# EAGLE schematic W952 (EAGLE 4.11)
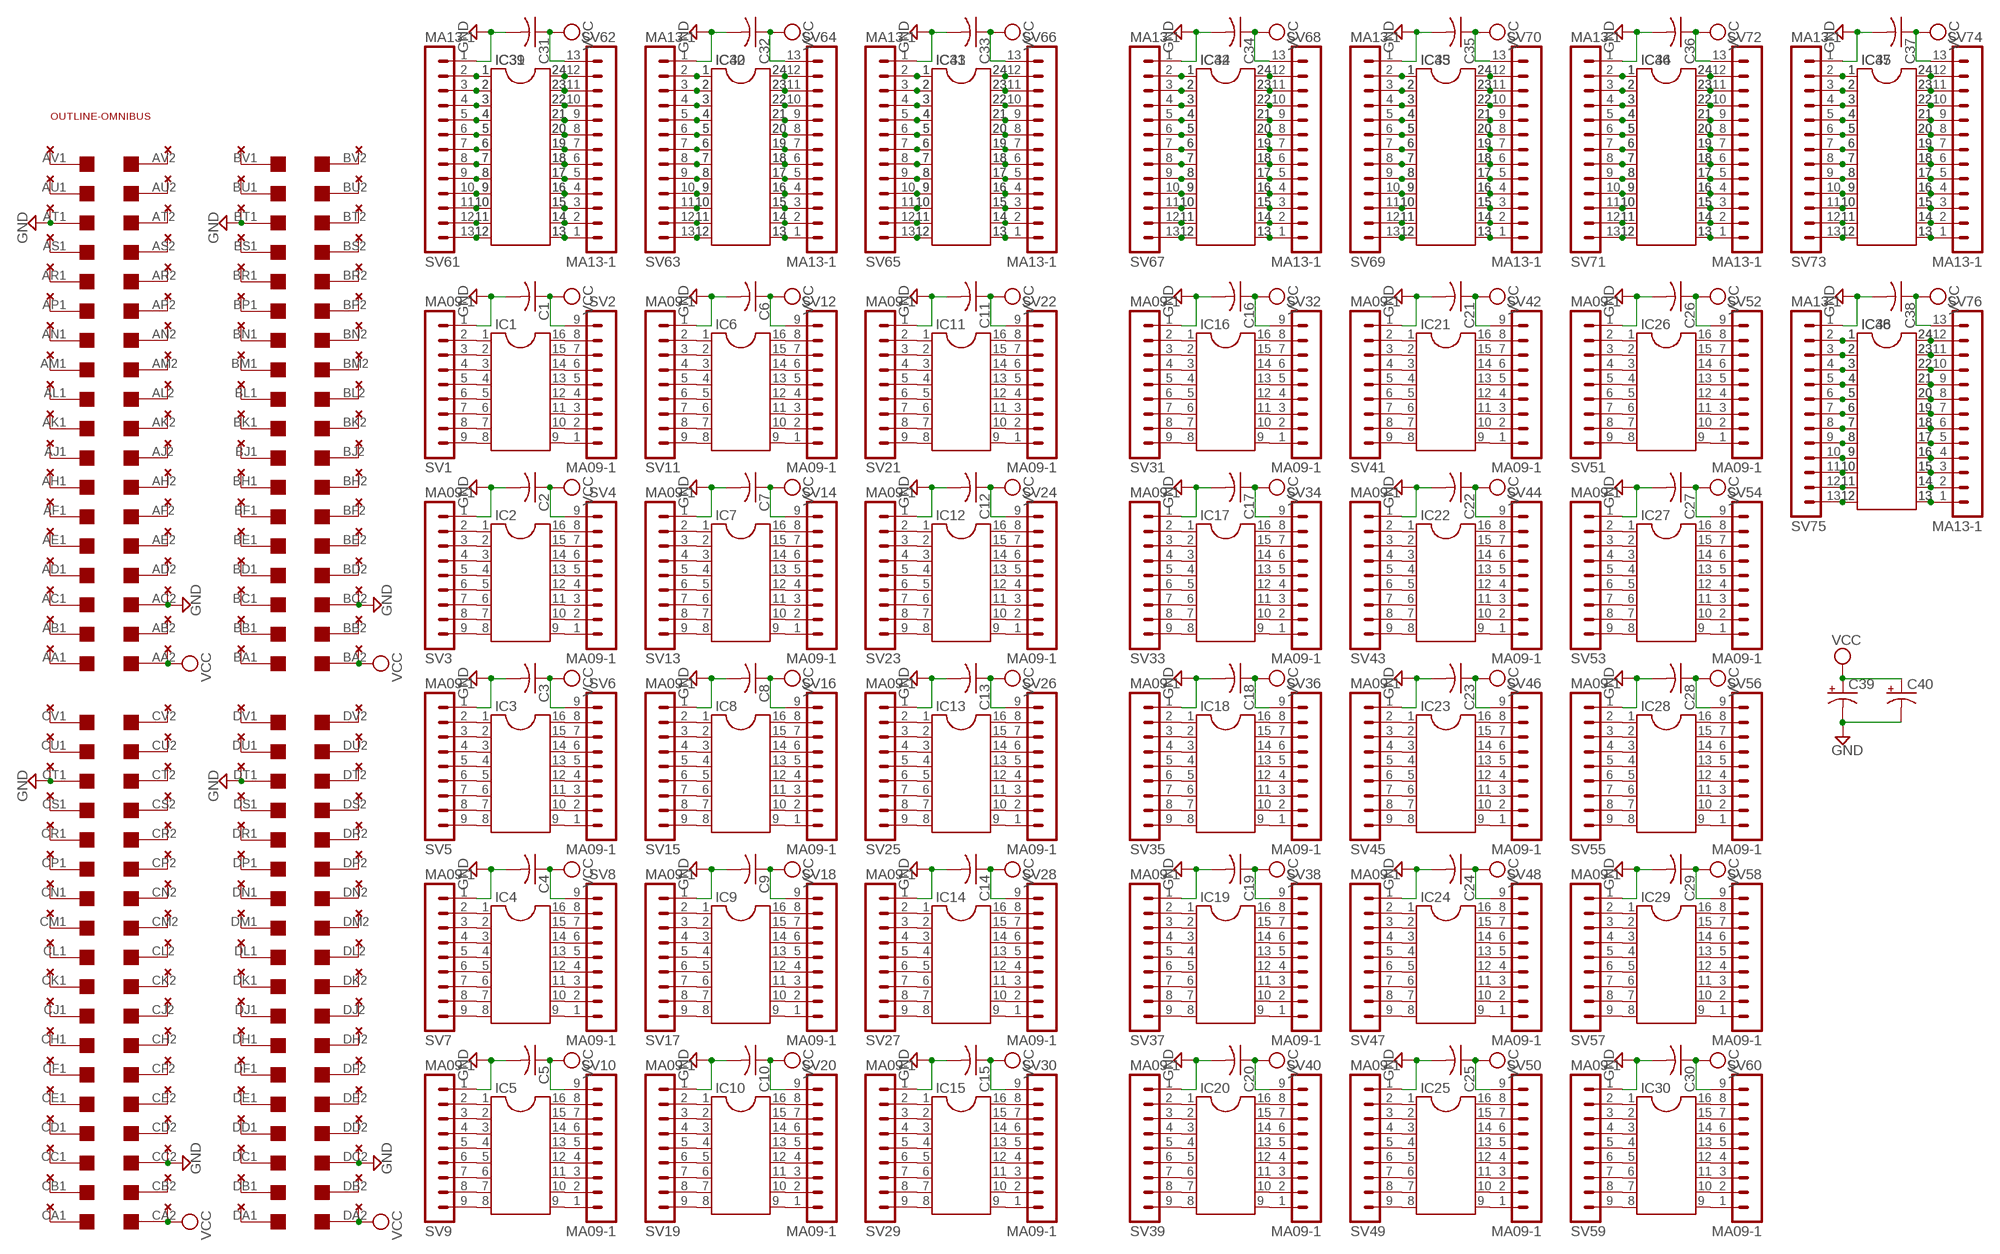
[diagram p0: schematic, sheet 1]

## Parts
C1  C-US075-032X103  [C075-032X103]
C2  C-US075-032X103  [C075-032X103]
C3  C-US075-032X103  [C075-032X103]
C4  C-US075-032X103  [C075-032X103]
C5  C-US075-032X103  [C075-032X103]
C6  C-US075-032X103  [C075-032X103]
C7  C-US075-032X103  [C075-032X103]
C8  C-US075-032X103  [C075-032X103]
C9  C-US075-032X103  [C075-032X103]
C10  C-US075-032X103  [C075-032X103]
C11  C-US075-032X103  [C075-032X103]
C12  C-US075-032X103  [C075-032X103]
C13  C-US075-032X103  [C075-032X103]
C14  C-US075-032X103  [C075-032X103]
C15  C-US075-032X103  [C075-032X103]
C16  C-US075-032X103  [C075-032X103]
C17  C-US075-032X103  [C075-032X103]
C18  C-US075-032X103  [C075-032X103]
C19  C-US075-032X103  [C075-032X103]
C20  C-US075-032X103  [C075-032X103]
C21  C-US075-032X103  [C075-032X103]
C22  C-US075-032X103  [C075-032X103]
C23  C-US075-032X103  [C075-032X103]
C24  C-US075-032X103  [C075-032X103]
C25  C-US075-032X103  [C075-032X103]
C26  C-US075-032X103  [C075-032X103]
C27  C-US075-032X103  [C075-032X103]
C28  C-US075-032X103  [C075-032X103]
C29  C-US075-032X103  [C075-032X103]
C30  C-US075-032X103  [C075-032X103]
C31  C-US075-032X103  [C075-032X103]
C32  C-US075-032X103  [C075-032X103]
C33  C-US075-032X103  [C075-032X103]
C34  C-US075-032X103  [C075-032X103]
C35  C-US075-032X103  [C075-032X103]
C36  C-US075-032X103  [C075-032X103]
C37  C-US075-032X103  [C075-032X103]
C38  C-US075-032X103  [C075-032X103]
C39  CPOL-USE15-5AXIAL  [E15-5]
C40  CPOL-USE15-5AXIAL  [E15-5]
IC1  DIL16S  [SOCKED-16]
IC2  DIL16S  [SOCKED-16]
IC3  DIL16S  [SOCKED-16]
IC4  DIL16S  [SOCKED-16]
IC5  DIL16S  [SOCKED-16]
IC6  DIL16S  [SOCKED-16]
IC7  DIL16S  [SOCKED-16]
IC8  DIL16S  [SOCKED-16]
IC9  DIL16S  [SOCKED-16]
IC10  DIL16S  [SOCKED-16]
IC11  DIL16S  [SOCKED-16]
IC12  DIL16S  [SOCKED-16]
IC13  DIL16S  [SOCKED-16]
IC14  DIL16S  [SOCKED-16]
IC15  DIL16S  [SOCKED-16]
IC16  DIL16S  [SOCKED-16]
IC17  DIL16S  [SOCKED-16]
IC18  DIL16S  [SOCKED-16]
IC19  DIL16S  [SOCKED-16]
IC20  DIL16S  [SOCKED-16]
IC21  DIL16S  [SOCKED-16]
IC22  DIL16S  [SOCKED-16]
IC23  DIL16S  [SOCKED-16]
IC24  DIL16S  [SOCKED-16]
IC25  DIL16S  [SOCKED-16]
IC26  DIL16S  [SOCKED-16]
IC27  DIL16S  [SOCKED-16]
IC28  DIL16S  [SOCKED-16]
IC29  DIL16S  [SOCKED-16]
IC30  DIL16S  [SOCKED-16]
IC31  DIL24-6  [DIL24-6]
IC32  DIL24-6  [DIL24-6]
IC33  DIL24-6  [DIL24-6]
IC34  DIL24-6  [DIL24-6]
IC35  DIL24-6  [DIL24-6]
IC36  DIL24-6  [DIL24-6]
IC37  DIL24-6  [DIL24-6]
IC38  DIL24-6  [DIL24-6]
IC39  DIL24-3  [DIL24-3]
IC40  DIL24-3  [DIL24-3]
IC41  DIL24-3  [DIL24-3]
IC42  DIL24-3  [DIL24-3]
IC43  DIL24-3  [DIL24-3]
IC44  DIL24-3  [DIL24-3]
IC45  DIL24-3  [DIL24-3]
IC46  DIL24-3  [DIL24-3]
SV1  MA09-1  [MA09-1]
SV2  MA09-1  [MA09-1]
SV3  MA09-1  [MA09-1]
SV4  MA09-1  [MA09-1]
SV5  MA09-1  [MA09-1]
SV6  MA09-1  [MA09-1]
SV7  MA09-1  [MA09-1]
SV8  MA09-1  [MA09-1]
SV9  MA09-1  [MA09-1]
SV10  MA09-1  [MA09-1]
SV11  MA09-1  [MA09-1]
SV12  MA09-1  [MA09-1]
SV13  MA09-1  [MA09-1]
SV14  MA09-1  [MA09-1]
SV15  MA09-1  [MA09-1]
SV16  MA09-1  [MA09-1]
SV17  MA09-1  [MA09-1]
SV18  MA09-1  [MA09-1]
SV19  MA09-1  [MA09-1]
SV20  MA09-1  [MA09-1]
SV21  MA09-1  [MA09-1]
SV22  MA09-1  [MA09-1]
SV23  MA09-1  [MA09-1]
SV24  MA09-1  [MA09-1]
SV25  MA09-1  [MA09-1]
SV26  MA09-1  [MA09-1]
SV27  MA09-1  [MA09-1]
SV28  MA09-1  [MA09-1]
SV29  MA09-1  [MA09-1]
SV30  MA09-1  [MA09-1]
SV31  MA09-1  [MA09-1]
SV32  MA09-1  [MA09-1]
SV33  MA09-1  [MA09-1]
SV34  MA09-1  [MA09-1]
SV35  MA09-1  [MA09-1]
SV36  MA09-1  [MA09-1]
SV37  MA09-1  [MA09-1]
SV38  MA09-1  [MA09-1]
SV39  MA09-1  [MA09-1]
SV40  MA09-1  [MA09-1]
SV41  MA09-1  [MA09-1]
SV42  MA09-1  [MA09-1]
SV43  MA09-1  [MA09-1]
SV44  MA09-1  [MA09-1]
SV45  MA09-1  [MA09-1]
SV46  MA09-1  [MA09-1]
SV47  MA09-1  [MA09-1]
SV48  MA09-1  [MA09-1]
SV49  MA09-1  [MA09-1]
SV50  MA09-1  [MA09-1]
SV51  MA09-1  [MA09-1]
SV52  MA09-1  [MA09-1]
SV53  MA09-1  [MA09-1]
SV54  MA09-1  [MA09-1]
SV55  MA09-1  [MA09-1]
SV56  MA09-1  [MA09-1]
SV57  MA09-1  [MA09-1]
SV58  MA09-1  [MA09-1]
SV59  MA09-1  [MA09-1]
SV60  MA09-1  [MA09-1]
SV61  MA13-1  [MA13-1]
SV62  MA13-1  [MA13-1]
SV63  MA13-1  [MA13-1]
SV64  MA13-1  [MA13-1]
SV65  MA13-1  [MA13-1]
SV66  MA13-1  [MA13-1]
SV67  MA13-1  [MA13-1]
SV68  MA13-1  [MA13-1]
SV69  MA13-1  [MA13-1]
SV70  MA13-1  [MA13-1]
SV71  MA13-1  [MA13-1]
SV72  MA13-1  [MA13-1]
SV73  MA13-1  [MA13-1]
SV74  MA13-1  [MA13-1]
SV75  MA13-1  [MA13-1]
SV76  MA13-1  [MA13-1]
U$1  QUAD  [EDGE-CON8]
U$2  THRU-HOLE2  [THRU-HOLE2]
U$3  THRU-HOLE2  [THRU-HOLE2]
U$4  THRU-HOLE2  [THRU-HOLE2]
U$5  THRU-HOLE2  [THRU-HOLE2]
U$8  OUTLINE-OMNIBUS  [OMNIBUS]

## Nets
GND [supply]: C1.2 C2.2 C3.2 C4.2 C5.2 C6.2 C7.2 C8.2 C9.2 C10.2 C11.2 C12.2 C13.2 C14.2 C15.2 C16.2 C17.2 C18.2 C19.2 C20.2 C21.2 C22.2 C23.2 C24.2 C25.2 C26.2 C27.2 C28.2 C29.2 C30.2 C31.2 C32.2 C33.2 C34.2 C35.2 C36.2 C37.2 C38.2 C39.- C40.- SV1.1 SV3.1 SV5.1 SV7.1 SV9.1 SV11.1 SV13.1 SV15.1 SV17.1 SV19.1 SV21.1 SV23.1 SV25.1 SV27.1 SV29.1 SV31.1 SV33.1 SV35.1 SV37.1 SV39.1 SV41.1 SV43.1 SV45.1 SV47.1 SV49.1 SV51.1 SV53.1 SV55.1 SV57.1 SV59.1 SV61.1 SV63.1 SV65.1 SV67.1 SV69.1 SV71.1 SV73.1 SV75.1 U$1.AC2 U$1.AT1 U$1.BC2 U$1.BT1 U$1.CC2 U$1.CT1 U$1.DC2 U$1.DT1 U$2.C1 U$2.T2 U$3.C1 U$3.T2 U$4.C1 U$4.T2 U$5.C1 U$5.T2
N$1: U$1.AK1 U$2.K2
N$2: U$1.AJ1 U$2.J2
N$3: U$1.AH1 U$2.H2
N$4: U$1.AL1 U$2.L2
N$5: U$1.AM1 U$2.M2
N$6: U$1.AN1 U$2.N2
N$7: U$1.AP1 U$2.P2
N$8: U$1.AF1 U$2.F2
N$9: U$1.AE1 U$2.E2
N$10: U$1.AD1 U$2.D2
N$11: U$1.AC1 U$2.C2
N$12: U$1.AR1 U$2.R2
N$13: U$1.AS1 U$2.S2
N$14: U$1.AB1 U$2.B2
N$15: U$1.AA1 U$2.A2
N$16: U$1.AU1 U$2.U2
N$17: U$1.AV1 U$2.V2
N$18: U$1.AV2 U$2.V1
N$19: U$1.AU2 U$2.U1
N$20: U$1.AT2 U$2.T1
N$21: U$1.AS2 U$2.S1
N$22: U$1.AR2 U$2.R1
N$23: U$1.AP2 U$2.P1
N$24: U$1.AN2 U$2.N1
N$25: U$1.AM2 U$2.M1
N$26: U$1.AL2 U$2.L1
N$27: U$1.AK2 U$2.K1
N$28: U$1.AJ2 U$2.J1
N$29: U$1.AH2 U$2.H1
N$30: U$1.AF2 U$2.F1
N$31: U$1.AE2 U$2.E1
N$32: U$1.AD2 U$2.D1
N$33: U$1.AB2 U$2.B1
N$34: U$1.BV1 U$3.V2
N$35: U$1.BU1 U$3.U2
N$36: U$1.BS1 U$3.S2
N$37: U$1.BR1 U$3.R2
N$38: U$1.BP1 U$3.P2
N$39: U$1.BN1 U$3.N2
N$40: U$1.BM1 U$3.M2
N$41: U$1.BL1 U$3.L2
N$42: U$1.BK1 U$3.K2
N$43: U$1.BJ1 U$3.J2
N$44: U$1.BH1 U$3.H2
N$45: U$1.BF1 U$3.F2
N$46: U$1.BE1 U$3.E2
N$47: U$1.BD1 U$3.D2
N$48: U$1.BC1 U$3.C2
N$49: U$1.BB1 U$3.B2
N$50: U$1.BA1 U$3.A2
N$51: U$1.BV2 U$3.V1
N$52: U$1.BU2 U$3.U1
N$53: U$1.BT2 U$3.T1
N$54: U$1.BS2 U$3.S1
N$55: U$1.BR2 U$3.R1
N$56: U$1.BP2 U$3.P1
N$57: U$1.BN2 U$3.N1
N$58: U$1.BM2 U$3.M1
N$59: U$1.BL2 U$3.L1
N$60: U$1.BK2 U$3.K1
N$61: U$1.BJ2 U$3.J1
N$62: U$1.BH2 U$3.H1
N$63: U$1.BF2 U$3.F1
N$64: U$1.BE2 U$3.E1
N$65: U$1.BD2 U$3.D1
N$66: U$1.BB2 U$3.B1
N$67: U$1.CV1 U$4.V2
N$68: U$1.CU1 U$4.U2
N$69: U$1.CS1 U$4.S2
N$70: U$1.CR1 U$4.R2
N$71: U$1.CP1 U$4.P2
N$72: U$1.CN1 U$4.N2
N$73: U$1.CM1 U$4.M2
N$74: U$1.CL1 U$4.L2
N$75: U$1.CK1 U$4.K2
N$76: U$1.CJ1 U$4.J2
N$77: U$1.CH1 U$4.H2
N$78: U$1.CF1 U$4.F2
N$79: U$1.CE1 U$4.E2
N$80: U$1.CD1 U$4.D2
N$81: U$1.CC1 U$4.C2
N$82: U$1.CB1 U$4.B2
N$83: U$1.CA1 U$4.A2
N$84: U$1.CV2 U$4.V1
N$85: U$1.CU2 U$4.U1
N$86: U$1.CT2 U$4.T1
N$87: U$1.CS2 U$4.S1
N$88: U$1.CR2 U$4.R1
N$89: U$1.CP2 U$4.P1
N$90: U$1.CN2 U$4.N1
N$91: U$1.CM2 U$4.M1
N$92: U$1.CL2 U$4.L1
N$93: U$1.CK2 U$4.K1
N$94: U$1.CJ2 U$4.J1
N$95: U$1.CH2 U$4.H1
N$96: U$1.CF2 U$4.F1
N$97: U$1.CE2 U$4.E1
N$98: U$1.CD2 U$4.D1
N$99: U$1.CB2 U$4.B1
N$100: U$1.DV1 U$5.V2
N$101: U$1.DU1 U$5.U2
N$102: U$1.DS1 U$5.S2
N$103: U$1.DR1 U$5.R2
N$104: U$1.DP1 U$5.P2
N$105: U$1.DN1 U$5.N2
N$106: U$1.DM1 U$5.M2
N$107: U$1.DL1 U$5.L2
N$108: U$1.DK1 U$5.K2
N$109: U$1.DJ1 U$5.J2
N$110: U$1.DH1 U$5.H2
N$111: U$1.DF1 U$5.F2
N$112: U$1.DE1 U$5.E2
N$113: U$1.DD1 U$5.D2
N$114: U$1.DC1 U$5.C2
N$115: U$1.DB1 U$5.B2
N$116: U$1.DA1 U$5.A2
N$117: U$1.DV2 U$5.V1
N$118: U$1.DU2 U$5.U1
N$119: U$1.DT2 U$5.T1
N$120: U$1.DS2 U$5.S1
N$121: U$1.DR2 U$5.R1
N$122: U$1.DP2 U$5.P1
N$123: U$1.DN2 U$5.N1
N$124: U$1.DM2 U$5.M1
N$125: U$1.DL2 U$5.L1
N$126: U$1.DK2 U$5.K1
N$127: U$1.DJ2 U$5.J1
N$128: U$1.DH2 U$5.H1
N$129: U$1.DF2 U$5.F1
N$130: U$1.DE2 U$5.E1
N$131: U$1.DD2 U$5.D1
N$132: U$1.DB2 U$5.B1
N$133: IC1.1 SV1.2
N$134: IC1.2 SV1.3
N$135: IC1.3 SV1.4
N$136: IC1.4 SV1.5
N$137: IC1.5 SV1.6
N$138: IC1.6 SV1.7
N$139: IC1.7 SV1.8
N$140: IC1.8 SV1.9
N$141: IC1.9 SV2.1
N$142: IC1.10 SV2.2
N$143: IC1.11 SV2.3
N$144: IC1.12 SV2.4
N$145: IC1.13 SV2.5
N$146: IC1.14 SV2.6
N$147: IC1.15 SV2.7
N$148: IC1.16 SV2.8
N$151: IC2.1 SV3.2
N$152: IC2.2 SV3.3
N$153: IC2.3 SV3.4
N$154: IC2.4 SV3.5
N$155: IC2.5 SV3.6
N$156: IC2.6 SV3.7
N$157: IC2.7 SV3.8
N$158: IC2.8 SV3.9
N$159: IC2.9 SV4.1
N$160: IC2.10 SV4.2
N$161: IC2.11 SV4.3
N$162: IC2.12 SV4.4
N$163: IC2.13 SV4.5
N$164: IC2.14 SV4.6
N$165: IC2.15 SV4.7
N$166: IC2.16 SV4.8
N$169: IC3.1 SV5.2
N$170: IC3.2 SV5.3
N$171: IC3.3 SV5.4
N$172: IC3.4 SV5.5
N$173: IC3.5 SV5.6
N$174: IC3.6 SV5.7
N$175: IC3.7 SV5.8
N$176: IC3.8 SV5.9
N$177: IC3.9 SV6.1
N$178: IC3.10 SV6.2
N$179: IC3.11 SV6.3
N$180: IC3.12 SV6.4
N$181: IC3.13 SV6.5
N$182: IC3.14 SV6.6
N$183: IC3.15 SV6.7
N$184: IC3.16 SV6.8
N$187: IC4.1 SV7.2
N$188: IC4.2 SV7.3
N$189: IC4.3 SV7.4
N$190: IC4.4 SV7.5
N$191: IC4.5 SV7.6
N$192: IC4.6 SV7.7
N$193: IC4.7 SV7.8
N$194: IC4.8 SV7.9
N$195: IC4.9 SV8.1
N$196: IC4.10 SV8.2
N$197: IC4.11 SV8.3
N$198: IC4.12 SV8.4
N$199: IC4.13 SV8.5
N$200: IC4.14 SV8.6
N$201: IC4.15 SV8.7
N$202: IC4.16 SV8.8
N$205: IC5.1 SV9.2
N$206: IC5.2 SV9.3
N$207: IC5.3 SV9.4
N$208: IC5.4 SV9.5
N$209: IC5.5 SV9.6
N$210: IC5.6 SV9.7
N$211: IC5.7 SV9.8
N$212: IC5.8 SV9.9
N$213: IC5.9 SV10.1
N$214: IC5.10 SV10.2
N$215: IC5.11 SV10.3
N$216: IC5.12 SV10.4
N$217: IC5.13 SV10.5
N$218: IC5.14 SV10.6
N$219: IC5.15 SV10.7
N$220: IC5.16 SV10.8
N$223: IC6.1 SV11.2
N$224: IC6.2 SV11.3
N$225: IC6.3 SV11.4
N$226: IC6.4 SV11.5
N$227: IC6.5 SV11.6
N$228: IC6.6 SV11.7
N$229: IC6.7 SV11.8
N$230: IC6.8 SV11.9
N$231: IC6.9 SV12.1
N$232: IC6.10 SV12.2
N$233: IC6.11 SV12.3
N$234: IC6.12 SV12.4
N$235: IC6.13 SV12.5
N$236: IC6.14 SV12.6
N$237: IC6.15 SV12.7
N$238: IC6.16 SV12.8
N$241: IC7.1 SV13.2
N$242: IC7.2 SV13.3
N$243: IC7.3 SV13.4
N$244: IC7.4 SV13.5
N$245: IC7.5 SV13.6
N$246: IC7.6 SV13.7
N$247: IC7.7 SV13.8
N$248: IC7.8 SV13.9
N$249: IC7.9 SV14.1
N$250: IC7.10 SV14.2
N$251: IC7.11 SV14.3
N$252: IC7.12 SV14.4
N$253: IC7.13 SV14.5
N$254: IC7.14 SV14.6
N$255: IC7.15 SV14.7
N$256: IC7.16 SV14.8
N$259: IC8.1 SV15.2
N$260: IC8.2 SV15.3
N$261: IC8.3 SV15.4
N$262: IC8.4 SV15.5
N$263: IC8.5 SV15.6
N$264: IC8.6 SV15.7
N$265: IC8.7 SV15.8
N$266: IC8.8 SV15.9
N$267: IC8.9 SV16.1
N$268: IC8.10 SV16.2
N$269: IC8.11 SV16.3
N$270: IC8.12 SV16.4
N$271: IC8.13 SV16.5
N$272: IC8.14 SV16.6
N$273: IC8.15 SV16.7
N$274: IC8.16 SV16.8
N$277: IC9.1 SV17.2
N$278: IC9.2 SV17.3
N$279: IC9.3 SV17.4
N$280: IC9.4 SV17.5
N$281: IC9.5 SV17.6
N$282: IC9.6 SV17.7
N$283: IC9.7 SV17.8
N$284: IC9.8 SV17.9
N$285: IC9.9 SV18.1
N$286: IC9.10 SV18.2
N$287: IC9.11 SV18.3
N$288: IC9.12 SV18.4
N$289: IC9.13 SV18.5
N$290: IC9.14 SV18.6
N$291: IC9.15 SV18.7
N$292: IC9.16 SV18.8
N$295: IC10.1 SV19.2
N$296: IC10.2 SV19.3
N$297: IC10.3 SV19.4
N$298: IC10.4 SV19.5
N$299: IC10.5 SV19.6
N$300: IC10.6 SV19.7
N$301: IC10.7 SV19.8
N$302: IC10.8 SV19.9
N$303: IC10.9 SV20.1
N$304: IC10.10 SV20.2
N$305: IC10.11 SV20.3
N$306: IC10.12 SV20.4
N$307: IC10.13 SV20.5
N$308: IC10.14 SV20.6
N$309: IC10.15 SV20.7
N$310: IC10.16 SV20.8
N$313: IC11.1 SV21.2
N$314: IC11.2 SV21.3
N$315: IC11.3 SV21.4
N$316: IC11.4 SV21.5
N$317: IC11.5 SV21.6
N$318: IC11.6 SV21.7
N$319: IC11.7 SV21.8
N$320: IC11.8 SV21.9
N$321: IC11.9 SV22.1
N$322: IC11.10 SV22.2
N$323: IC11.11 SV22.3
N$324: IC11.12 SV22.4
N$325: IC11.13 SV22.5
N$326: IC11.14 SV22.6
N$327: IC11.15 SV22.7
N$328: IC11.16 SV22.8
N$331: IC12.1 SV23.2
N$332: IC12.2 SV23.3
N$333: IC12.3 SV23.4
N$334: IC12.4 SV23.5
N$335: IC12.5 SV23.6
N$336: IC12.6 SV23.7
N$337: IC12.7 SV23.8
N$338: IC12.8 SV23.9
N$339: IC12.9 SV24.1
N$340: IC12.10 SV24.2
N$341: IC12.11 SV24.3
N$342: IC12.12 SV24.4
N$343: IC12.13 SV24.5
N$344: IC12.14 SV24.6
N$345: IC12.15 SV24.7
N$346: IC12.16 SV24.8
N$349: IC13.1 SV25.2
N$350: IC13.2 SV25.3
N$351: IC13.3 SV25.4
N$352: IC13.4 SV25.5
N$353: IC13.5 SV25.6
N$354: IC13.6 SV25.7
N$355: IC13.7 SV25.8
N$356: IC13.8 SV25.9
N$357: IC13.9 SV26.1
N$358: IC13.10 SV26.2
N$359: IC13.11 SV26.3
N$360: IC13.12 SV26.4
N$361: IC13.13 SV26.5
N$362: IC13.14 SV26.6
N$363: IC13.15 SV26.7
N$364: IC13.16 SV26.8
N$367: IC14.1 SV27.2
N$368: IC14.2 SV27.3
N$369: IC14.3 SV27.4
N$370: IC14.4 SV27.5
N$371: IC14.5 SV27.6
N$372: IC14.6 SV27.7
N$373: IC14.7 SV27.8
N$374: IC14.8 SV27.9
N$375: IC14.9 SV28.1
N$376: IC14.10 SV28.2
N$377: IC14.11 SV28.3
N$378: IC14.12 SV28.4
N$379: IC14.13 SV28.5
N$380: IC14.14 SV28.6
N$381: IC14.15 SV28.7
N$382: IC14.16 SV28.8
N$385: IC15.1 SV29.2
N$386: IC15.2 SV29.3
N$387: IC15.3 SV29.4
N$388: IC15.4 SV29.5
N$389: IC15.5 SV29.6
N$390: IC15.6 SV29.7
N$391: IC15.7 SV29.8
N$392: IC15.8 SV29.9
N$393: IC15.9 SV30.1
N$394: IC15.10 SV30.2
N$395: IC15.11 SV30.3
N$396: IC15.12 SV30.4
N$397: IC15.13 SV30.5
N$398: IC15.14 SV30.6
N$399: IC15.15 SV30.7
N$400: IC15.16 SV30.8
N$403: IC16.1 SV31.2
N$404: IC16.2 SV31.3
N$405: IC16.3 SV31.4
N$406: IC16.4 SV31.5
N$407: IC16.5 SV31.6
N$408: IC16.6 SV31.7
N$409: IC16.7 SV31.8
N$410: IC16.8 SV31.9
N$411: IC16.9 SV32.1
N$412: IC16.10 SV32.2
N$413: IC16.11 SV32.3
N$414: IC16.12 SV32.4
N$415: IC16.13 SV32.5
N$416: IC16.14 SV32.6
N$417: IC16.15 SV32.7
N$418: IC16.16 SV32.8
N$421: IC17.1 SV33.2
N$422: IC17.2 SV33.3
N$423: IC17.3 SV33.4
N$424: IC17.4 SV33.5
N$425: IC17.5 SV33.6
N$426: IC17.6 SV33.7
N$427: IC17.7 SV33.8
N$428: IC17.8 SV33.9
N$429: IC17.9 SV34.1
N$430: IC17.10 SV34.2
N$431: IC17.11 SV34.3
N$432: IC17.12 SV34.4
N$433: IC17.13 SV34.5
N$434: IC17.14 SV34.6
N$435: IC17.15 SV34.7
N$436: IC17.16 SV34.8
N$439: IC18.1 SV35.2
N$440: IC18.2 SV35.3
N$441: IC18.3 SV35.4
N$442: IC18.4 SV35.5
N$443: IC18.5 SV35.6
N$444: IC18.6 SV35.7
N$445: IC18.7 SV35.8
N$446: IC18.8 SV35.9
N$447: IC18.9 SV36.1
N$448: IC18.10 SV36.2
N$449: IC18.11 SV36.3
N$450: IC18.12 SV36.4
N$451: IC18.13 SV36.5
N$452: IC18.14 SV36.6
N$453: IC18.15 SV36.7
N$454: IC18.16 SV36.8
N$457: IC19.1 SV37.2
N$458: IC19.2 SV37.3
N$459: IC19.3 SV37.4
N$460: IC19.4 SV37.5
N$461: IC19.5 SV37.6
N$462: IC19.6 SV37.7
N$463: IC19.7 SV37.8
N$464: IC19.8 SV37.9
N$465: IC19.9 SV38.1
N$466: IC19.10 SV38.2
N$467: IC19.11 SV38.3
N$468: IC19.12 SV38.4
N$469: IC19.13 SV38.5
N$470: IC19.14 SV38.6
N$471: IC19.15 SV38.7
N$472: IC19.16 SV38.8
N$475: IC20.1 SV39.2
N$476: IC20.2 SV39.3
N$477: IC20.3 SV39.4
N$478: IC20.4 SV39.5
N$479: IC20.5 SV39.6
N$480: IC20.6 SV39.7
N$481: IC20.7 SV39.8
N$482: IC20.8 SV39.9
N$483: IC20.9 SV40.1
N$484: IC20.10 SV40.2
N$485: IC20.11 SV40.3
N$486: IC20.12 SV40.4
N$487: IC20.13 SV40.5
N$488: IC20.14 SV40.6
N$489: IC20.15 SV40.7
N$490: IC20.16 SV40.8
N$493: IC21.1 SV41.2
N$494: IC21.2 SV41.3
N$495: IC21.3 SV41.4
N$496: IC21.4 SV41.5
N$497: IC21.5 SV41.6
N$498: IC21.6 SV41.7
N$499: IC21.7 SV41.8
N$500: IC21.8 SV41.9
N$501: IC21.9 SV42.1
N$502: IC21.10 SV42.2
N$503: IC21.11 SV42.3
N$504: IC21.12 SV42.4
N$505: IC21.13 SV42.5
N$506: IC21.14 SV42.6
N$507: IC21.15 SV42.7
N$508: IC21.16 SV42.8
N$511: IC22.1 SV43.2
N$512: IC22.2 SV43.3
N$513: IC22.3 SV43.4
N$514: IC22.4 SV43.5
N$515: IC22.5 SV43.6
N$516: IC22.6 SV43.7
N$517: IC22.7 SV43.8
N$518: IC22.8 SV43.9
N$519: IC22.9 SV44.1
N$520: IC22.10 SV44.2
N$521: IC22.11 SV44.3
N$522: IC22.12 SV44.4
N$523: IC22.13 SV44.5
N$524: IC22.14 SV44.6
N$525: IC22.15 SV44.7
N$526: IC22.16 SV44.8
N$529: IC23.1 SV45.2
N$530: IC23.2 SV45.3
N$531: IC23.3 SV45.4
N$532: IC23.4 SV45.5
N$533: IC23.5 SV45.6
N$534: IC23.6 SV45.7
N$535: IC23.7 SV45.8
N$536: IC23.8 SV45.9
N$537: IC23.9 SV46.1
N$538: IC23.10 SV46.2
N$539: IC23.11 SV46.3
N$540: IC23.12 SV46.4
N$541: IC23.13 SV46.5
N$542: IC23.14 SV46.6
N$543: IC23.15 SV46.7
N$544: IC23.16 SV46.8
N$547: IC24.1 SV47.2
N$548: IC24.2 SV47.3
N$549: IC24.3 SV47.4
N$550: IC24.4 SV47.5
N$551: IC24.5 SV47.6
N$552: IC24.6 SV47.7
N$553: IC24.7 SV47.8
N$554: IC24.8 SV47.9
N$555: IC24.9 SV48.1
N$556: IC24.10 SV48.2
N$557: IC24.11 SV48.3
N$558: IC24.12 SV48.4
N$559: IC24.13 SV48.5
N$560: IC24.14 SV48.6
N$561: IC24.15 SV48.7
N$562: IC24.16 SV48.8
N$565: IC25.1 SV49.2
N$566: IC25.2 SV49.3
N$567: IC25.3 SV49.4
N$568: IC25.4 SV49.5
N$569: IC25.5 SV49.6
N$570: IC25.6 SV49.7
N$571: IC25.7 SV49.8
N$572: IC25.8 SV49.9
N$573: IC25.9 SV50.1
N$574: IC25.10 SV50.2
N$575: IC25.11 SV50.3
N$576: IC25.12 SV50.4
N$577: IC25.13 SV50.5
N$578: IC25.14 SV50.6
N$579: IC25.15 SV50.7
N$580: IC25.16 SV50.8
N$583: IC26.1 SV51.2
N$584: IC26.2 SV51.3
N$585: IC26.3 SV51.4
N$586: IC26.4 SV51.5
N$587: IC26.5 SV51.6
N$588: IC26.6 SV51.7
N$589: IC26.7 SV51.8
N$590: IC26.8 SV51.9
N$591: IC26.9 SV52.1
N$592: IC26.10 SV52.2
N$593: IC26.11 SV52.3
N$594: IC26.12 SV52.4
N$595: IC26.13 SV52.5
N$596: IC26.14 SV52.6
N$597: IC26.15 SV52.7
N$598: IC26.16 SV52.8
N$601: IC27.1 SV53.2
N$602: IC27.2 SV53.3
N$603: IC27.3 SV53.4
N$604: IC27.4 SV53.5
N$605: IC27.5 SV53.6
N$606: IC27.6 SV53.7
N$607: IC27.7 SV53.8
N$608: IC27.8 SV53.9
N$609: IC27.9 SV54.1
N$610: IC27.10 SV54.2
N$611: IC27.11 SV54.3
N$612: IC27.12 SV54.4
N$613: IC27.13 SV54.5
N$614: IC27.14 SV54.6
N$615: IC27.15 SV54.7
N$616: IC27.16 SV54.8
N$619: IC28.1 SV55.2
N$620: IC28.2 SV55.3
N$621: IC28.3 SV55.4
N$622: IC28.4 SV55.5
N$623: IC28.5 SV55.6
N$624: IC28.6 SV55.7
N$625: IC28.7 SV55.8
N$626: IC28.8 SV55.9
N$627: IC28.9 SV56.1
N$628: IC28.10 SV56.2
N$629: IC28.11 SV56.3
N$630: IC28.12 SV56.4
N$631: IC28.13 SV56.5
N$632: IC28.14 SV56.6
N$633: IC28.15 SV56.7
N$634: IC28.16 SV56.8
N$637: IC29.1 SV57.2
N$638: IC29.2 SV57.3
N$639: IC29.3 SV57.4
N$640: IC29.4 SV57.5
N$641: IC29.5 SV57.6
N$642: IC29.6 SV57.7
N$643: IC29.7 SV57.8
N$644: IC29.8 SV57.9
N$645: IC29.9 SV58.1
N$646: IC29.10 SV58.2
N$647: IC29.11 SV58.3
N$648: IC29.12 SV58.4
N$649: IC29.13 SV58.5
N$650: IC29.14 SV58.6
N$651: IC29.15 SV58.7
N$652: IC29.16 SV58.8
N$655: IC30.1 SV59.2
N$656: IC30.2 SV59.3
N$657: IC30.3 SV59.4
N$658: IC30.4 SV59.5
N$659: IC30.5 SV59.6
N$660: IC30.6 SV59.7
N$661: IC30.7 SV59.8
N$662: IC30.8 SV59.9
N$663: IC30.9 SV60.1
N$664: IC30.10 SV60.2
N$665: IC30.11 SV60.3
N$666: IC30.12 SV60.4
N$667: IC30.13 SV60.5
N$668: IC30.14 SV60.6
N$669: IC30.15 SV60.7
N$670: IC30.16 SV60.8
N$673: IC31.1 IC39.1 SV61.2
N$674: IC31.2 IC39.2 SV61.3
N$675: IC31.3 IC39.3 SV61.4
N$676: IC31.4 IC39.4 SV61.5
N$677: IC31.5 IC39.5 SV61.6
N$678: IC31.6 IC39.6 SV61.7
N$679: IC31.7 IC39.7 SV61.8
N$680: IC31.8 IC39.8 SV61.9
N$681: IC31.9 IC39.9 SV61.10
N$682: IC31.10 IC39.10 SV61.11
N$683: IC31.11 IC39.11 SV61.12
N$684: IC31.12 IC39.12 SV61.13
N$685: IC31.13 IC39.13 SV62.1
N$686: IC31.14 IC39.14 SV62.2
N$687: IC31.15 IC39.15 SV62.3
N$688: IC31.16 IC39.16 SV62.4
N$689: IC31.17 IC39.17 SV62.5
N$690: IC31.18 IC39.18 SV62.6
N$691: IC31.19 IC39.19 SV62.7
N$692: IC31.20 IC39.20 SV62.8
N$693: IC31.21 IC39.21 SV62.9
N$694: IC31.22 IC39.22 SV62.10
N$695: IC31.23 IC39.23 SV62.11
N$696: IC31.24 IC39.24 SV62.12
N$699: IC32.1 IC40.1 SV63.2
N$700: IC32.2 IC40.2 SV63.3
N$701: IC32.3 IC40.3 SV63.4
N$702: IC32.4 IC40.4 SV63.5
N$703: IC32.5 IC40.5 SV63.6
N$704: IC32.6 IC40.6 SV63.7
N$705: IC32.7 IC40.7 SV63.8
N$706: IC32.8 IC40.8 SV63.9
N$707: IC32.9 IC40.9 SV63.10
N$708: IC32.10 IC40.10 SV63.11
N$709: IC32.11 IC40.11 SV63.12
N$710: IC32.12 IC40.12 SV63.13
N$711: IC32.13 IC40.13 SV64.1
N$712: IC32.14 IC40.14 SV64.2
N$713: IC32.15 IC40.15 SV64.3
N$714: IC32.16 IC40.16 SV64.4
N$715: IC32.17 IC40.17 SV64.5
N$716: IC32.18 IC40.18 SV64.6
N$717: IC32.19 IC40.19 SV64.7
N$718: IC32.20 IC40.20 SV64.8
N$719: IC32.21 IC40.21 SV64.9
N$720: IC32.22 IC40.22 SV64.10
N$721: IC32.23 IC40.23 SV64.11
N$722: IC32.24 IC40.24 SV64.12
N$725: IC33.1 IC41.1 SV65.2
N$726: IC33.2 IC41.2 SV65.3
N$727: IC33.3 IC41.3 SV65.4
N$728: IC33.4 IC41.4 SV65.5
N$729: IC33.5 IC41.5 SV65.6
N$730: IC33.6 IC41.6 SV65.7
N$731: IC33.7 IC41.7 SV65.8
N$732: IC33.8 IC41.8 SV65.9
N$733: IC33.9 IC41.9 SV65.10
N$734: IC33.10 IC41.10 SV65.11
N$735: IC33.11 IC41.11 SV65.12
N$736: IC33.12 IC41.12 SV65.13
N$737: IC33.13 IC41.13 SV66.1
N$738: IC33.14 IC41.14 SV66.2
N$739: IC33.15 IC41.15 SV66.3
N$740: IC33.16 IC41.16 SV66.4
N$741: IC33.17 IC41.17 SV66.5
N$742: IC33.18 IC41.18 SV66.6
N$743: IC33.19 IC41.19 SV66.7
N$744: IC33.20 IC41.20 SV66.8
N$745: IC33.21 IC41.21 SV66.9
N$746: IC33.22 IC41.22 SV66.10
N$747: IC33.23 IC41.23 SV66.11
N$748: IC33.24 IC41.24 SV66.12
N$751: IC34.1 IC42.1 SV67.2
N$752: IC34.2 IC42.2 SV67.3
N$753: IC34.3 IC42.3 SV67.4
N$754: IC34.4 IC42.4 SV67.5
N$755: IC34.5 IC42.5 SV67.6
N$756: IC34.6 IC42.6 SV67.7
N$757: IC34.7 IC42.7 SV67.8
N$758: IC34.8 IC42.8 SV67.9
N$759: IC34.9 IC42.9 SV67.10
N$760: IC34.10 IC42.10 SV67.11
N$761: IC34.11 IC42.11 SV67.12
N$762: IC34.12 IC42.12 SV67.13
N$763: IC34.13 IC42.13 SV68.1
N$764: IC34.14 IC42.14 SV68.2
N$765: IC34.15 IC42.15 SV68.3
N$766: IC34.16 IC42.16 SV68.4
N$767: IC34.17 IC42.17 SV68.5
N$768: IC34.18 IC42.18 SV68.6
N$769: IC34.19 IC42.19 SV68.7
N$770: IC34.20 IC42.20 SV68.8
N$771: IC34.21 IC42.21 SV68.9
N$772: IC34.22 IC42.22 SV68.10
N$773: IC34.23 IC42.23 SV68.11
N$774: IC34.24 IC42.24 SV68.12
N$777: IC35.1 IC43.1 SV69.2
N$778: IC35.2 IC43.2 SV69.3
N$779: IC35.3 IC43.3 SV69.4
N$780: IC35.4 IC43.4 SV69.5
N$781: IC35.5 IC43.5 SV69.6
N$782: IC35.6 IC43.6 SV69.7
N$783: IC35.7 IC43.7 SV69.8
N$784: IC35.8 IC43.8 SV69.9
N$785: IC35.9 IC43.9 SV69.10
N$786: IC35.10 IC43.10 SV69.11
N$787: IC35.11 IC43.11 SV69.12
N$788: IC35.12 IC43.12 SV69.13
N$789: IC35.13 IC43.13 SV70.1
N$790: IC35.14 IC43.14 SV70.2
N$791: IC35.15 IC43.15 SV70.3
N$792: IC35.16 IC43.16 SV70.4
N$793: IC35.17 IC43.17 SV70.5
N$794: IC35.18 IC43.18 SV70.6
N$795: IC35.19 IC43.19 SV70.7
N$796: IC35.20 IC43.20 SV70.8
N$797: IC35.21 IC43.21 SV70.9
N$798: IC35.22 IC43.22 SV70.10
N$799: IC35.23 IC43.23 SV70.11
N$800: IC35.24 IC43.24 SV70.12
N$803: IC36.1 IC44.1 SV71.2
N$804: IC36.2 IC44.2 SV71.3
N$805: IC36.3 IC44.3 SV71.4
N$806: IC36.4 IC44.4 SV71.5
N$807: IC36.5 IC44.5 SV71.6
N$808: IC36.6 IC44.6 SV71.7
N$809: IC36.7 IC44.7 SV71.8
N$810: IC36.8 IC44.8 SV71.9
N$811: IC36.9 IC44.9 SV71.10
N$812: IC36.10 IC44.10 SV71.11
N$813: IC36.11 IC44.11 SV71.12
N$814: IC36.12 IC44.12 SV71.13
N$815: IC36.13 IC44.13 SV72.1
N$816: IC36.14 IC44.14 SV72.2
N$817: IC36.15 IC44.15 SV72.3
N$818: IC36.16 IC44.16 SV72.4
N$819: IC36.17 IC44.17 SV72.5
N$820: IC36.18 IC44.18 SV72.6
N$821: IC36.19 IC44.19 SV72.7
N$822: IC36.20 IC44.20 SV72.8
N$823: IC36.21 IC44.21 SV72.9
N$824: IC36.22 IC44.22 SV72.10
N$825: IC36.23 IC44.23 SV72.11
N$826: IC36.24 IC44.24 SV72.12
N$829: IC37.1 IC45.1 SV73.2
N$830: IC37.2 IC45.2 SV73.3
N$831: IC37.3 IC45.3 SV73.4
N$832: IC37.4 IC45.4 SV73.5
N$833: IC37.5 IC45.5 SV73.6
N$834: IC37.6 IC45.6 SV73.7
N$835: IC37.7 IC45.7 SV73.8
N$836: IC37.8 IC45.8 SV73.9
N$837: IC37.9 IC45.9 SV73.10
N$838: IC37.10 IC45.10 SV73.11
N$839: IC37.11 IC45.11 SV73.12
N$840: IC37.12 IC45.12 SV73.13
N$841: IC37.13 IC45.13 SV74.1
N$842: IC37.14 IC45.14 SV74.2
N$843: IC37.15 IC45.15 SV74.3
N$844: IC37.16 IC45.16 SV74.4
N$845: IC37.17 IC45.17 SV74.5
N$846: IC37.18 IC45.18 SV74.6
N$847: IC37.19 IC45.19 SV74.7
N$848: IC37.20 IC45.20 SV74.8
N$849: IC37.21 IC45.21 SV74.9
N$850: IC37.22 IC45.22 SV74.10
N$851: IC37.23 IC45.23 SV74.11
N$852: IC37.24 IC45.24 SV74.12
N$855: IC38.1 IC46.1 SV75.2
N$856: IC38.2 IC46.2 SV75.3
N$857: IC38.3 IC46.3 SV75.4
N$858: IC38.4 IC46.4 SV75.5
N$859: IC38.5 IC46.5 SV75.6
N$860: IC38.6 IC46.6 SV75.7
N$861: IC38.7 IC46.7 SV75.8
N$862: IC38.8 IC46.8 SV75.9
N$863: IC38.9 IC46.9 SV75.10
N$864: IC38.10 IC46.10 SV75.11
N$865: IC38.11 IC46.11 SV75.12
N$866: IC38.12 IC46.12 SV75.13
N$867: IC38.13 IC46.13 SV76.1
N$868: IC38.14 IC46.14 SV76.2
N$869: IC38.15 IC46.15 SV76.3
N$870: IC38.16 IC46.16 SV76.4
N$871: IC38.17 IC46.17 SV76.5
N$872: IC38.18 IC46.18 SV76.6
N$873: IC38.19 IC46.19 SV76.7
N$874: IC38.20 IC46.20 SV76.8
N$875: IC38.21 IC46.21 SV76.9
N$876: IC38.22 IC46.22 SV76.10
N$877: IC38.23 IC46.23 SV76.11
N$878: IC38.24 IC46.24 SV76.12
VCC [supply]: C1.1 C2.1 C3.1 C4.1 C5.1 C6.1 C7.1 C8.1 C9.1 C10.1 C11.1 C12.1 C13.1 C14.1 C15.1 C16.1 C17.1 C18.1 C19.1 C20.1 C21.1 C22.1 C23.1 C24.1 C25.1 C26.1 C27.1 C28.1 C29.1 C30.1 C31.1 C32.1 C33.1 C34.1 C35.1 C36.1 C37.1 C38.1 C39.+ C40.+ SV2.9 SV4.9 SV6.9 SV8.9 SV10.9 SV12.9 SV14.9 SV16.9 SV18.9 SV20.9 SV22.9 SV24.9 SV26.9 SV28.9 SV30.9 SV32.9 SV34.9 SV36.9 SV38.9 SV40.9 SV42.9 SV44.9 SV46.9 SV48.9 SV50.9 SV52.9 SV54.9 SV56.9 SV58.9 SV60.9 SV62.13 SV64.13 SV66.13 SV68.13 SV70.13 SV72.13 SV74.13 SV76.13 U$1.AA2 U$1.BA2 U$1.CA2 U$1.DA2 U$2.A1 U$3.A1 U$4.A1 U$5.A1

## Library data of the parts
C1-C38 = rcl:C-US: CAPACITOR, American symbol
C39 C40 = rcl:CPOL-US: POLARIZED CAPACITOR, American symbol
IC1-IC30 = ic-package:DIL16: Dual In Line
IC31-IC46 = ic-package:DIL24: Dual In Line
SV1-SV60 = dec-con:MA09-1: Pin Header (.125" spacing)
SV61-SV76 = dec-con:MA13-1: Pin Header (.125" spacing)
U$1 = dec-con:QUAD: Quad-Height DEC board
U$2-U$5 = dec-con:THRU-HOLE2: Thru-Hole addition to double-sided edge connector.
U$8 = dec-con:OUTLINE-*: Board outlines for DEC boards.

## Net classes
0 default: width 0.508 mm
1 supply: width 0.762 mm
